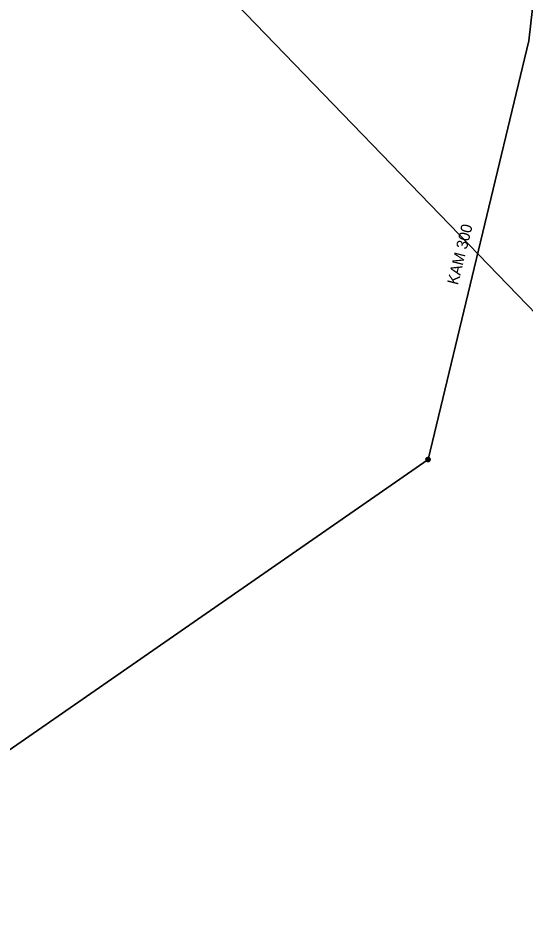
# Model space of a CAD drawing. Extents: x -867121 to -866743, y -1014362 to -1014088.
# Drawn here: x -866844.4 to -866794.7, y -1014313.4 to -1014225.9 of the extents above; entities that cross this region are included whole.
import ezdxf

# ---------------------------------------------------------------- set-up
doc = ezdxf.new("R2010")
doc.units = 0
doc.header["$LTSCALE"] = 0.44
for name, color, linetype, lineweight in [('1', 7, 'Continuous', 35), ('21', 7, 'Continuous', 35), ('32', 7, 'Continuous', 13)]:
    doc.layers.add(name, color=color, linetype=linetype, lineweight=lineweight)

msp = doc.modelspace()

# ---------------------------------------------------------------- linework, layer by layer
at = {"layer": '1'}
msp.add_lwpolyline([(-866792.574, -1014256.008), (-866841.087, -1014205.753), (-866857.467, -1014153.141), (-866859.393, -1014135.973), (-866869.502, -1014132.716), (-866897.758, -1014124.346), (-866897.929, -1014124.295)], dxfattribs=at)
at = {"layer": '21'}
msp.add_lwpolyline([(-866867.906, -1014313.414), (-866804.195, -1014269.207), (-866794.318, -1014228.125), (-866791.378, -1014202.173), (-866784.04, -1014170.77), (-866768.345, -1014133.735)], dxfattribs=at)
at = {"layer": '32'}
for points in [[(-866803.967, -1014269.207), (-866803.973, -1014269.155), (-866803.99, -1014269.105), (-866804.019, -1014269.061), (-866804.056, -1014269.024), (-866804.101, -1014268.997), (-866804.151, -1014268.98), (-866804.204, -1014268.976), (-866804.255, -1014268.983), (-866804.304, -1014269.002), (-866804.348, -1014269.031), (-866804.384, -1014269.07), (-866804.41, -1014269.115), (-866804.426, -1014269.166), (-866804.429, -1014269.218), (-866804.421, -1014269.27), (-866804.401, -1014269.319), (-866804.37, -1014269.362), (-866804.331, -1014269.396), (-866804.285, -1014269.422), (-866804.233, -1014269.436), (-866804.181, -1014269.438), (-866804.13, -1014269.428), (-866804.081, -1014269.407), (-866804.039, -1014269.376), (-866804.005, -1014269.335), (-866803.981, -1014269.289), (-866803.968, -1014269.238)], [(-866803.997, -1014269.207), (-866804.003, -1014269.158), (-866804.02, -1014269.112), (-866804.048, -1014269.072), (-866804.085, -1014269.04), (-866804.129, -1014269.018), (-866804.177, -1014269.007), (-866804.226, -1014269.007), (-866804.272, -1014269.02), (-866804.316, -1014269.044), (-866804.352, -1014269.077), (-866804.379, -1014269.118), (-866804.395, -1014269.165), (-866804.399, -1014269.214), (-866804.392, -1014269.262), (-866804.373, -1014269.307), (-866804.343, -1014269.347), (-866804.304, -1014269.378), (-866804.261, -1014269.398), (-866804.213, -1014269.408), (-866804.164, -1014269.406), (-866804.117, -1014269.391), (-866804.074, -1014269.366), (-866804.039, -1014269.332), (-866804.014, -1014269.29), (-866804, -1014269.243)], [(-866804.027, -1014269.207), (-866804.032, -1014269.162), (-866804.049, -1014269.12), (-866804.078, -1014269.085), (-866804.114, -1014269.058), (-866804.156, -1014269.041), (-866804.201, -1014269.036), (-866804.245, -1014269.042), (-866804.287, -1014269.061), (-866804.321, -1014269.089), (-866804.348, -1014269.126), (-866804.365, -1014269.168), (-866804.369, -1014269.213), (-866804.362, -1014269.258), (-866804.343, -1014269.299), (-866804.314, -1014269.333), (-866804.277, -1014269.359), (-866804.233, -1014269.375), (-866804.189, -1014269.378), (-866804.144, -1014269.37), (-866804.103, -1014269.35), (-866804.07, -1014269.321), (-866804.044, -1014269.283), (-866804.03, -1014269.24)], [(-866804.057, -1014269.207), (-866804.061, -1014269.166), (-866804.08, -1014269.129), (-866804.107, -1014269.098), (-866804.142, -1014269.077), (-866804.182, -1014269.066), (-866804.223, -1014269.068), (-866804.262, -1014269.081), (-866804.296, -1014269.105), (-866804.321, -1014269.137), (-866804.336, -1014269.175), (-866804.338, -1014269.216), (-866804.331, -1014269.256), (-866804.311, -1014269.292), (-866804.282, -1014269.321), (-866804.245, -1014269.34), (-866804.205, -1014269.348), (-866804.164, -1014269.344), (-866804.125, -1014269.329), (-866804.093, -1014269.303), (-866804.071, -1014269.269), (-866804.058, -1014269.23)], [(-866804.087, -1014269.207), (-866804.092, -1014269.171), (-866804.11, -1014269.139), (-866804.136, -1014269.114), (-866804.169, -1014269.099), (-866804.206, -1014269.096), (-866804.24, -1014269.104), (-866804.272, -1014269.124), (-866804.294, -1014269.152), (-866804.308, -1014269.186), (-866804.308, -1014269.223), (-866804.297, -1014269.258), (-866804.276, -1014269.287), (-866804.245, -1014269.308), (-866804.211, -1014269.318), (-866804.174, -1014269.316), (-866804.14, -1014269.302), (-866804.113, -1014269.279), (-866804.093, -1014269.247), (-866804.087, -1014269.212)], [(-866804.117, -1014269.207), (-866804.122, -1014269.176), (-866804.139, -1014269.15), (-866804.164, -1014269.133), (-866804.195, -1014269.126), (-866804.226, -1014269.13), (-866804.253, -1014269.147), (-866804.271, -1014269.171), (-866804.279, -1014269.202), (-866804.275, -1014269.232), (-866804.26, -1014269.26), (-866804.235, -1014269.279), (-866804.206, -1014269.288), (-866804.174, -1014269.285), (-866804.147, -1014269.271), (-866804.127, -1014269.247), (-866804.117, -1014269.218)], [(-866804.147, -1014269.207), (-866804.152, -1014269.183), (-866804.169, -1014269.165), (-866804.191, -1014269.156), (-866804.216, -1014269.159), (-866804.237, -1014269.173), (-866804.248, -1014269.195), (-866804.248, -1014269.22), (-866804.235, -1014269.241), (-866804.216, -1014269.255), (-866804.191, -1014269.258), (-866804.168, -1014269.249), (-866804.152, -1014269.231)], [(-866804.177, -1014269.207), (-866804.182, -1014269.192), (-866804.196, -1014269.186), (-866804.212, -1014269.19), (-866804.218, -1014269.204), (-866804.215, -1014269.219), (-866804.201, -1014269.228), (-866804.186, -1014269.225), (-866804.177, -1014269.213)]]:
    msp.add_lwpolyline(points, close=True, dxfattribs=at)

# ---------------------------------------------------------------- texts
at = {"layer": '1'}
msp.add_text('KAM 300 ', height=1.1, rotation=76, dxfattribs=at).set_placement((-866801.275, -1014252.14))

doc.saveas('drawing.dxf')
